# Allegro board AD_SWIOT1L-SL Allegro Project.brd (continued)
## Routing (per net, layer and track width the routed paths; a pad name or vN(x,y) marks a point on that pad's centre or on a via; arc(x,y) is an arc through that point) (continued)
AD74413R_GPO_A_ISO: length 40.2
  TOP w0.178: U2.19 31.37,39.61 32.81,41.06 32.81,43.77 34.74,45.7 42.28,45.7 v1(44.16,47.58) ; U14.16 v1(48.65,66.31)
  BOTTOM w0.178: v1(48.65,66.31) 48.65,52.07 v1(44.16,47.58)
AD74413R_GPO_B: length 33.9
  TOP w0.178: v1(43.46,91.31) 41.57,93.2 35.93,93.2 33.65,95.49 31.36,95.49 31.06,95.19 U1.46 ; U14.6 v1(48,76.01)
  BOTTOM w0.178: v1(43.46,91.31) 43.46,84.76 48,80.22 v1(48,76.01)
AD74413R_GPO_B_ISO: length 40
  TOP w0.178: U2.20 30.87,39.65 32.4,41.19 32.4,43.91 34.58,46.08 41.89,46.08 v1(43.45,47.65) ; U14.15 v1(48,65.97)
  BOTTOM w0.178: v1(43.45,47.65) 48,52.19 v1(48,65.97)
AD74413R_GPO_C: length 31.9
  TOP w0.178: U1.48 33.32,94.19 35.4,92.11 40.78,92.11 42.81,90.08 v1(42.92,90.08) ; U14.7 v1(47.35,76.39)
  BOTTOM w0.178: v1(42.92,90.08) 42.92,84.69 47.35,80.26 v1(47.35,76.39)
AD74413R_GPO_C_ISO: length 39.8
  TOP w0.178: U14.14 v1(47.35,66.31) ; v1(43.41,48.41) 41.47,46.47 34.42,46.47 32.02,44.06 32.02,41.4 30.37,39.74 U2.21
  BOTTOM w0.178: v1(47.35,66.31) 47.35,52.34 v1(43.41,48.41)
AD74413R_GPO_D: length 30.8
  TOP w0.178: v1(42.33,89.57) 40.43,91.47 35.17,91.47 32.96,93.69 U1.49 ; v1(46.7,76.01) U14.8
  BOTTOM w0.178: v1(46.7,76.01) 46.7,80.3 42.33,84.67 v1(42.33,89.57)
AD74413R_GPO_D_ISO: length 39.6
  TOP w0.178: U14.13 v1(46.7,65.29) ; U2.22 29.87,39.79 31.64,41.57 31.64,44.22 34.26,46.85 40.99,46.85 v1(42.61,48.47)
  BOTTOM w0.178: v1(42.61,48.47) 46.7,52.56 v1(46.7,65.29)
AD74413R_LDAC: length 31.4
  TOP w0.152: v1(54.47,78.42) 46.29,78.42 45.45,79.26 U1.100
  TOP w0.203: v1(58.73,60.44) U25.37
  BOTTOM w0.152: v1(54.47,78.42) 56.66,76.23 56.66,65.36 58.73,63.29 v1(58.73,60.44)
AD74413R_LDAC_ISO: length 63
  TOP w0.203: U2.58 29.37,28.72 30.5,27.59 30.5,23.43 31.94,21.98 43.12,21.98 v1(49.98,28.84) ; v1(64.63,51.41) 63.93,51.41 63.73,51.61 U25.22 ; R78.1 55.01,46.27 v1(55.01,45.54)
  BOTTOM w0.203: v1(64.63,51.41) 61.5,51.41 55.63,45.54 v1(55.01,45.54) 55.01,43.67 50.99,39.66 50.99,29.85 v1(49.98,28.84)
AD74413R_RESET: length 30.6
  TOP w0.152: U1.103 46.95,79.31 47.31,78.95 54.7,78.95 v1(55.26,78.39)
  TOP w0.203: v1(59.38,60.87) 59.38,60.31 59.23,60.16 U25.36
  BOTTOM w0.152: v1(59.38,60.87) 59.38,63.46 57.04,65.79 57.04,76.62 v1(55.26,78.39)
AD74413R_RESET_ISO: length 61.4
  TOP w0.203: R75.2 v1(54.88,47.41) ; v1(64.84,52.12) U25.23 ; v1(47.06,30.95) 47.06,29.37 41.54,23.86 32.91,23.86 32.2,24.57 32.2,28.23 31.37,29.06 U2.62
  BOTTOM w0.203: v1(47.06,30.95) 48.71,29.3 49.32,29.3 50.38,30.36 50.38,39.86 54.45,43.93 54.45,46.98 v1(54.88,47.41) 56.74,47.41 61.45,52.12 v1(64.84,52.12)
ADIN1110_RESET: length 15.9
  TOP w0.178: U1.121 50.38,88.19 50.37,88.18 50.09,88.18 v1(49.71,87.8) ; U8.5 v1(60.7,83.3)
  BOTTOM w0.178: v1(60.7,83.3) 57.77,83.3 56.2,84.87 53.51,84.87 50.57,87.8 v1(49.71,87.8)
ADT75_OS__ALLERT: length 24.2
  TOP w0.203: v1(13.65,102.26) U4.3 15.92,102.26 R94.2 ; v1(28.34,98.26) 28.77,98.69 U1.39
  BOTTOM w0.203: v1(13.65,102.26) 13.09,102.26 12.4,101.56 12.4,100.63 14.77,98.26 v1(28.34,98.26)
ALDO1V8: length 6.5
  TOP w0.279: U2.10 36.11,35.22 36.69,35.79 C22.1 C25.2
ALDO5V: length 4.6
  TOP w0.279: C21.1 36.83,35.21 36.34,34.72 U2.9
CABLE+: length 10.2
  TOP w0.762: 89.93,92.67 P3.1 ; P3.1 91.18,93.91 ; P3.1 89.93,95.16 ; P3.1 88.69,93.91
  TOP w0.787: R73.1 89.38,86.15 90.57,87.33 L1.4
CABLE-: length 10.2
  TOP w0.762: P3.2 92.5,93.91 ; P3.2 93.74,92.67 ; P3.2 93.74,95.16 ; P3.2 94.99,93.91
  TOP w0.787: L1.3 93.11,87.33 94.29,86.15 R74.1
CASCODE_A: length 6.4
  TOP w0.305: Q1.3 33.42,25.03 33.11,25.34 33.11,29.64 32.81,29.95 U2.64
CASCODE_B: length 4.1
  TOP w0.305: U2.17 32.97,38.99 34.22,40.23 Q2.3
CASCODE_C: length 6.4
  TOP w0.305: Q3.3 23.82,43.9 24.12,43.6 24.12,39.29 24.42,38.99 U2.32
CASCODE_D: length 4.1
  TOP w0.305: U2.49 24.36,29.95 23.01,28.6 Q4.3
CCOMP_A: length 16.6
  TOP w0.254: U2.63 31.87,29.45 v1(32.5,28.81)
  TOP w0.305: v1(40.58,28.08) 41.09,28.58 C1.1
  BOTTOM w0.254: v1(40.58,28.08) 40.58,26.55 37.99,23.96 35.22,23.96 32.5,26.68 v1(32.5,28.81)
CCOMP_B: length 13
  TOP w0.254: U2.18 31.87,39.45 32.45,40.04 v1(33.01,40.04)
  TOP w0.279: v1(41.07,40.65) C4.1
  BOTTOM w0.305: v1(41.07,40.65) 39.39,42.33 34.64,42.33 33.01,40.69 v1(33.01,40.04)
CCOMP_C: length 17
  TOP w0.279: U2.31 25.37,39.49 v1(24.73,40.12)
  TOP w0.305: C2.1 v1(16.14,41.11)
  BOTTOM w0.305: v1(24.73,40.12) 24.73,42.6 22.21,45.12 19.27,45.12 16.14,42 v1(16.14,41.11)
CCOMP_D: length 12.7
  TOP w0.279: v1(16.16,28.29) C3.1 ; v1(24.65,28.56) 25.37,29.27 U2.50
  BOTTOM w0.254: v1(16.16,28.29) 17.87,26.58 22.67,26.58 v1(24.65,28.56)
CH_1: length 13.3
  TOP w0.483: R9.2 R1.2 R17.1
  TOP w0.635: P6.1 41.95,8.11 ; P6.1 41.95,5.62 ; P6.1 40.71,6.87 ; P6.1 43.2,6.87
  TOP w0.762: v1(45.2,30.49) v1(44.49,30.49) C1.2 39.73,30.49 R17.1
  vias: v1(34.87,18.33) v1(34.87,17.56) v1(35.02,53.45) v1(35.02,52.69) v1(35.69,18.33) v1(35.69,17.56) v1(35.78,53.45) v1(35.78,52.69)
CH_2: length 10.9
  TOP w0.483: R18.1 R3.2 R11.2
  TOP w0.635: P6.3 35.58,6.87 ; P6.3 34.33,5.62 ; P6.3 34.33,8.11 ; P6.3 33.09,6.87
  TOP w0.762: R18.1 39.73,38.22 C4.2 v1(42.18,38.22) v1(42.89,38.22)
  vias: v1(27.25,18.33) v1(27.25,17.56) v1(28.07,18.33) v1(28.07,17.56) v1(34.95,59.15) v1(34.95,58.39) v1(35.71,59.15) v1(35.71,58.39)
CH_3: length 11.4
  TOP w0.483: R19.1 R5.2 R13.2
  TOP w0.635: P6.5 26.71,8.11 ; P6.5 26.71,5.62 ; P6.5 27.96,6.87 ; P6.5 25.47,6.87
  TOP w0.762: v1(13.86,38.44) v1(14.57,38.44) C2.2 17.5,38.44 R19.1
  vias: v1(19.63,18.33) v1(19.63,17.56) v1(20.45,18.33) v1(20.45,17.56) v1(21.5,59.15) v1(21.51,58.39) v1(22.17,59.15) v1(22.17,58.39)
CH_4: length 13.9
  TOP w0.483: R15.2 R7.2 R20.1
  TOP w0.635: P6.7 20.34,6.87 ; P6.7 17.85,6.87 ; P6.7 19.09,8.11 ; P6.7 19.09,5.62
  TOP w0.762: v1(11.34,30.72) v1(12.05,30.72) C3.2 17.5,30.72 R20.1
  vias: v1(12.01,18.33) v1(12.01,17.56) v1(12.83,18.33) v1(12.83,17.56) v1(21.46,53.46) v1(21.46,52.7) v1(22.22,53.46) v1(22.22,52.7)
DATA_AND_POWER_N: length 28.3
  TOP w0.305: R71.2 81.39,84.77 C46.2 v1(82.7,84.98)
  TOP w0.787: L1.2 93.11,83.27 94.29,84.45 R74.2
  BOTTOM w0.305: v1(93.11,79.99) 92.5,79.99 92.12,80.37 92.12,82.28 90.92,83.47 81.09,83.47 80.41,84.16 80.41,85.3 81.07,85.96 82.32,85.96 82.7,85.59 v1(82.7,84.98)
DATA_AND_POWER_P: length 29.2
  TOP w0.305: R72.2 81.39,87.68 C45.2 v1(82.7,87.47)
  TOP w0.787: L1.1 90.57,83.27 89.38,84.45 R73.2
  BOTTOM w0.305: v1(82.7,87.47) 82.7,86.86 82.33,86.5 80.81,86.5 79.87,85.56 79.87,83.93 80.86,82.94 90.69,82.94 91.57,82.06 91.57,80.39 91.18,79.99 v1(90.57,79.99)
DATA_N: length 7.2
  TOP w0.305: R71.1 79.89,84.77 C46.1 78.68,84.98 78.33,85.33 D19.1 R23.2 R24.2
DATA_P: length 7.2
  TOP w0.305: R22.2 R25.2 D5.1 78.33,87.12 78.68,87.47 C45.1 79.89,87.68 R72.1
DLDO1V8: length 3.5
  TOP w0.254: U2.57 28.87,28.36
  TOP w0.508: 28.87,28.36 C23.1 C130.2
DLDO_1P1: length 4
  TOP w0.254: U8.23 62.2,90.92 61.95,91.17 61.7,90.92 U8.24
  TOP w0.457: 61.95,91.17 61.95,92.09 C60.2 C58.1
FIELD_POWER_DETECTED: length 43.4
  TOP w0.152: v1(22.95,75.04) 22.95,76.13 23.74,76.92 26.74,76.92 31.94,82.13 39.87,82.13 40.45,81.54 U1.90
  TOP w0.203: U18.6 4.79,75.39 v1(4.79,75.4)
  BOTTOM w0.203: v1(4.79,75.4) 5.32,75.93 6.57,75.93 7.85,74.65 22.56,74.65 v1(22.95,75.04)
FIELD_POWER_DETECTED_ISO: length 83.5
  TOP w0.203: U18.3 v1(4.79,66.94) ; v1(51.68,54.06) 51.58,53.96 51.58,44.03 v1(55.9,39.71)
  BOTTOM w0.203: v1(55.9,39.71) 55.9,37.37 S2.2 ; v1(4.79,66.94) 5.19,66.54 9.15,66.54 10.4,67.8 48.61,67.8 49.62,66.79 49.62,56.12 v1(51.68,54.06)
FLED: length 46.7
  TOP w0.178: DS2.C 5.58,43.62 v1(5.58,43.62) 4.97,44.23 4.97,46.26 5.5,46.8 11.22,46.8 14.34,49.92 25.51,49.92 27.33,51.74 U3.4 ; v1(5.58,38.54) 5.58,38.54 DS4.C ; DS6.C 5.58,33.46 v1(5.58,33.46) ; DS8.C v1(5.58,28.38)
  BOTTOM w0.305: v1(5.58,28.38) v1(5.58,33.46) v1(5.58,38.54) v1(5.58,43.62)
G1: length 11
  TOP w0.203: U3.18 32.13,55.72 39.26,55.72 39.78,55.2 39.78,53.01 39.58,52.81 Q6.4
G2: length 7.5
  TOP w0.203: U3.19 32.11,56.15 38.4,56.15 38.96,56.71 Q5.4
G3: length 11.1
  TOP w0.203: Q7.4 17.53,59.06 17.33,58.85 17.33,56.69 17.87,56.15 25.06,56.15 U3.42
G4: length 7.6
  TOP w0.203: U3.43 25.04,55.72 18.69,55.72 18.16,55.18 Q8.4
GATE: length 7.5
  TOP w0.254: U19.12 93.09,55.74 93.76,55.74 v1(93.77,55.74)
  TOP w0.305: Q9.4 v1(97.96,55.31) 98.7,54.57 R40.2
  BOTTOM w0.305: v1(93.77,55.74) 97.52,55.74 v1(97.96,55.31)
HYP_CLK: length 45
  TOP w0.152: v1(18,94.57) 17.52,94.57 17.06,94.11 17.06,91.71 17.31,91.45 17.31,90.77 17.47,90.62 U10.B2 ; v1(23.66,94.22) 23.99,93.88 23.99,88.73 26.99,85.73 29.92,85.73 U1.65 ; U9.B2 6.04,90.62 5.89,90.77 5.89,91.45 5.64,91.71 5.64,94.11 6.1,94.57 v1(6.58,94.57)
  BOTTOM w0.152: v1(6.58,94.57) 6.58,95.05 7.88,96.35 10.63,96.35 12.87,94.12 17.06,94.12 17.52,94.57 v1(18,94.57) 18,95.05 18.61,95.67 20.3,95.67 20.73,95.23 21.29,95.23 21.72,95.67 23.48,95.67 23.99,95.16 23.99,94.55 v1(23.66,94.22)
HYP_CLKN: length 45
  TOP w0.152: U10.B1 16.91,90.77 16.91,91.28 16.65,91.54 16.65,94.28 17.23,94.86 v1(17.23,95.34) ; v1(24.74,94.22) 24.4,93.88 24.4,88.9 27.16,86.14 29.92,86.14 U1.64 ; v1(5.81,95.34) 5.81,94.86 5.23,94.28 5.23,91.54 5.48,91.28 5.48,90.77 U9.B1
  BOTTOM w0.152: v1(24.74,94.22) 24.4,94.56 24.4,95.33 23.65,96.07 18.45,96.07 17.71,95.34 v1(17.23,95.34) 17.23,94.86 16.9,94.52 13.04,94.52 10.8,96.76 7.71,96.76 6.29,95.34 v1(5.81,95.34)
HYP_CS0N: length 29.3
  TOP w0.152: v1(19.4,93.2) 18.76,92.57 U10.A3 ; U1.52 v1(31.18,92.19)
  BOTTOM w0.152: v1(19.4,93.2) 19.88,92.72 20.15,92.72 20.77,93.34 21.01,93.34 21.21,93.14 21.21,92.92 20.8,92.52 20.8,92.3 21.02,92.08 21.24,92.08 21.63,92.48 21.87,92.48 22.07,92.27 22.07,92.06 21.67,91.65 21.67,91.44 21.88,91.22 22.1,91.22 22.57,91.69 22.81,91.69 23.01,91.49 23.01,91.27 22.53,90.79 22.53,90.57 22.75,90.36 22.96,90.36 23.46,90.85 23.7,90.85 23.9,90.65 23.9,90.44 23.39,89.93 23.39,89.71 23.69,89.42 24.29,89.42 24.44,89.57 24.44,90.13 24.6,90.28 24.9,90.28 25.05,90.13 25.05,89.57 25.21,89.42 27.8,89.42 28.17,89.79 28.17,90 27.8,90.37 27.8,90.61 28.01,90.81 28.22,90.81 28.6,90.43 28.82,90.43 29.03,90.65 29.03,90.86 28.6,91.3 28.6,91.51 28.82,91.73 29.03,91.73 29.47,91.29 29.68,91.29 29.9,91.51 29.9,91.73 29.51,92.11 29.51,92.32 29.73,92.54 29.95,92.54 30.3,92.19 v1(31.18,92.19)
HYP_CS1N: length 29.3
  TOP w0.152: v1(8.1,95.11) R82.2 8.1,93.06 7.34,92.29 U9.A3 ; U1.44 v1(28.74,96.19)
  BOTTOM w0.152: v1(8.1,95.11) 10,93.2 18.48,93.2 19.09,93.81 21.2,93.81 22.04,92.97 27.09,92.97 28.21,94.09 28.21,95.65 v1(28.74,96.19)
HYP_D0: length 42.2
  TOP w0.152: v2(32.71,87.94) 32.71,89.98 30.99,91.69 U1.53 ; U10.D3 v2(18.29,89.09) ; U9.D3 v2(6.87,89.09)
  BOTTOM w0.152: v2(32.71,87.94) 32.71,87 29.38,83.68 25.92,83.68 24.79,84.81 23.56,84.81 23.41,84.96 23.41,85.28 23.25,85.43 22.95,85.43 22.8,85.28 22.8,84.96 22.65,84.81 22.1,84.81 18.79,88.12 18.79,88.59 v2(18.29,89.09) 17.79,89.6 16.75,89.6 16.22,90.13 15.53,90.13 15,89.59 13.58,89.59 10.15,86.17 9.26,86.17 7.71,87.72 7.71,88.6 7.23,89.09 v2(6.87,89.09)
HYP_D1: length 42.1
  TOP w0.152: U9.D2 v2(5.87,89.09) ; U1.58 31.11,89.19 31.82,88.48 31.82,87.74 32.76,86.8 33.18,86.8 v2(33.2,86.82) ; U10.D2 v2(17.29,89.09)
  BOTTOM w0.152: v2(33.2,86.82) 32.68,86.3 32.68,86.29 29.58,83.19 23.08,83.19 20.41,85.87 20.19,85.87 19.97,85.65 19.76,85.65 19.54,85.87 19.54,86.08 19.76,86.3 19.76,86.51 18.53,87.74 18.07,87.74 17.29,88.51 v2(17.29,89.09) 16.95,89.09 16.56,88.7 13.22,88.7 11.65,87.12 11.65,86.34 11.01,85.71 9.08,85.71 7.13,87.66 6.62,87.66 6.36,87.92 6.36,88.6 v2(5.87,89.09)
HYP_D2: length 42.2
  TOP w0.152: U1.62 31.05,87.19 32.68,85.56 34.13,85.56 34.43,85.86 v2(34.43,87.89) ; U10.C4 v2(20.23,90.09) ; U9.C4 v2(8.8,90.09)
  BOTTOM w0.152: v2(8.8,90.09) 10.46,90.09 11.35,90.97 11.35,91.19 10.98,91.56 10.98,91.77 11.2,91.99 11.42,91.99 11.78,91.62 12,91.62 12.72,92.34 18.86,92.34 19.73,91.47 19.73,90.59 v2(20.23,90.09) 20.96,90.09 22.47,88.58 24.78,88.58 25.8,87.56 28.97,87.56 29.28,87.88 29.28,89.44 30.37,90.53 31.79,90.53 v2(34.43,87.89)
HYP_D3: length 42.1
  TOP w0.152: v2(32.58,83.93) 31.32,85.19 U1.66 ; U10.D4 v2(20.23,88.15) ; U9.D4 v2(8.8,88.15)
  BOTTOM w0.152: v2(8.8,88.15) 9.23,88.58 10.43,88.58 13.35,91.5 18.51,91.5 18.8,91.2 18.8,90.19 19.73,89.26 19.73,88.65 v2(20.23,88.15) 20.74,87.64 24.45,87.64 25.52,86.57 28.95,86.57 29.99,85.53 30.57,85.53 32.07,87.03 32.07,88.15 32.43,88.5 33,88.5 34.51,87 34.51,84.51 33.92,83.93 v2(32.58,83.93)
HYP_D4: length 42.3
  TOP w0.152: U10.D5 v2(21.23,88.15) ; U1.56 31.22,90.19 v2(31.74,89.67) ; U9.D5 v2(9.8,89.09)
  BOTTOM w0.152: v2(9.8,89.09) 10.2,89.09 13.02,91.91 18.71,91.91 19.27,91.35 19.27,90.33 20.05,89.54 20.69,89.54 21.23,89.01 v2(21.23,88.15) 24.65,88.15 25.75,87.05 29.11,87.05 30.2,85.96 30.42,85.96 30.63,86.18 30.63,86.39 29.65,87.37 29.65,87.59 29.87,87.8 30.09,87.8 31.06,86.82 31.28,86.82 31.47,87.01 31.47,87.28 29.67,89.08 29.67,89.3 29.87,89.5 30.11,89.5 31.39,88.22 31.61,88.22 31.82,88.44 31.82,88.65 30.77,89.71 30.77,89.92 31.02,90.17 31.24,90.17 v2(31.74,89.67)
HYP_D5: length 42.2
  TOP w0.152: U9.E3 v2(6.87,87.15) ; U10.E3 v2(18.29,87.15) ; U1.59 30.97,88.69 31.38,88.27 31.38,87.54 32.83,86.09 v2(33.19,86.09)
  BOTTOM w0.152: v2(6.87,87.15) 8.8,85.23 11.27,85.23 12.16,86.11 12.16,86.88 12.77,87.49 13.73,87.49 13.88,87.65 13.88,87.94 14.03,88.1 14.34,88.1 14.49,87.94 14.49,87.65 14.64,87.49 15.01,87.49 15.69,88.17 17.01,88.17 18.03,87.15 v2(18.29,87.15) 18.83,86.62 18.83,85.49 19.57,84.74 19.79,84.74 20.09,85.05 20.31,85.05 20.53,84.83 20.53,84.62 20.22,84.31 20.22,84.1 20.44,83.88 20.65,83.88 20.96,84.19 21.2,84.19 21.4,83.98 21.4,83.77 21.08,83.45 21.08,83.23 21.58,82.74 29.83,82.74 v2(33.19,86.09)
HYP_D6: length 42.1
  TOP w0.152: U1.63 30.86,86.69 v2(32.7,84.84) ; U10.E2 v2(17.29,87.15) ; U9.E2 v2(5.87,87.15)
  BOTTOM w0.152: v2(5.87,87.15) 6.39,86.63 6.39,86.01 7.74,84.67 14.19,84.67 14.9,85.38 14.9,86.57 16.02,87.69 16.76,87.69 v2(17.29,87.15) 17.8,86.64 17.8,84.71 18.27,84.24 18.49,84.24 18.84,84.6 19.06,84.6 19.27,84.38 19.27,84.17 18.91,83.8 18.91,83.56 19.11,83.35 19.32,83.35 19.71,83.73 19.92,83.73 20.14,83.52 20.14,83.3 19.78,82.95 19.78,82.73 20.32,82.19 30.05,82.19 v2(32.7,84.84)
HYP_D7: length 42.1
  TOP w0.152: U10.E1 v2(16.29,87.15) ; U9.E1 v2(4.87,87.15) ; U1.67 31.03,84.69 31.94,83.78 v2(31.94,83.27)
  BOTTOM w0.152: v2(4.87,87.15) 5.35,86.67 5.35,85.89 7.13,84.11 14.49,84.11 15.48,85.1 15.48,86.35 16.29,87.16 v2(16.29,87.15) 16.77,86.67 16.77,84.88 17.21,84.44 17.21,84.22 16.9,83.92 16.9,83.7 17.12,83.49 17.34,83.49 17.64,83.79 17.86,83.79 18.07,83.58 18.07,83.36 17.79,83.08 17.79,82.87 18.01,82.65 18.22,82.65 18.5,82.93 18.72,82.93 18.94,82.71 18.94,82.5 18.68,82.24 18.68,82.03 18.9,81.81 19.11,81.81 19.37,82.07 19.58,82.07 19.98,81.67 30.34,81.67 v2(31.94,83.27)
HYP_RESET: length 33
  TOP w0.152: U1.50 31.86,93.19 32.32,92.72 v2(32.32,91.27) ; U9.A4 v2(8.8,92.09) ; U10.A4 v2(20.26,92.12)
  BOTTOM w0.152: v2(32.32,91.27) 32.04,90.99 30.06,90.99 28.64,89.57 28.64,88.81 27.85,88.02 25.97,88.02 25,88.99 23.4,88.99 v2(20.26,92.12) 19.71,92.12 19.04,92.8 9.51,92.8 v2(8.8,92.09)
HYP_RWDS: length 42.2
  TOP w0.152: U10.C3 v2(18.29,90.09) ; U9.C3 v2(6.87,90.09) ; U1.68 28.39,84.19 v2(28.18,84.39)
  BOTTOM w0.152: v2(6.87,90.09) 8.17,88.79 8.17,87.94 9.48,86.63 10.03,86.63 14.01,90.61 17.08,90.61 17.77,90.61 v2(18.29,90.09) 19.27,89.11 19.27,88.35 21.6,86.01 23.46,86.01 23.66,86.21 23.66,86.72 23.89,86.95 24.48,86.95 24.73,86.7 24.73,85.35 24.88,85.2 25.21,85.2 25.36,85.35 25.36,85.73 25.51,85.89 25.82,85.89 25.97,85.73 25.97,84.26 26.12,84.11 26.43,84.11 26.58,84.26 26.58,85.73 26.73,85.89 27.04,85.89 27.19,85.73 27.19,84.67 27.34,84.51 27.65,84.51 27.8,84.67 27.8,85.73 27.95,85.89 29.05,85.89 29.35,85.58 29.35,84.62 29.12,84.39 v2(28.18,84.39)
I2C1_SCL: length 34.4
  TOP w0.203: v1(39.63,98.59) 39.95,98.92 U1.20 ; v1(13.34,101.61) U4.2 R95.2
  BOTTOM w0.203: v1(13.34,101.61) 15.58,99.36 35.03,99.36 36.44,97.95 38.99,97.95 v1(39.63,98.59)
I2C1_SDA: length 36.1
  TOP w0.203: v1(13.04,100.96) U4.1 15.92,100.96 R96.2 ; U1.19 v1(40.45,98.59)
  BOTTOM w0.203: v1(40.45,98.59) 39.26,97.39 36.18,97.39 34.66,98.92 15.07,98.92 v1(13.04,100.96)
INT: length 13.9
  TOP w0.178: v1(50.22,91.19) U1.127 ; U8.25 61.2,91.25 v1(61.2,91.25)
  BOTTOM w0.178: v1(50.22,91.19) 53.4,91.19 54.24,92.03 60.42,92.03 v1(61.2,91.25)
L1: length 37.2
  TOP w0.178: U3.8 29.33,51.13 26.3,48.09 15.03,48.09 9.59,42.65 9.59,33.46 8.52,32.39 8.52,31.2 8.27,30.95 R33.2
L2: length 32.1
  TOP w0.178: R32.2 8.63,36.03 9.08,36.48 9.08,42.78 14.85,48.55 26.09,48.55 28.83,51.29 U3.7
L3: length 26.6
  TOP w0.178: U3.6 28.33,51.46 25.88,49.01 14.67,49.01 8.6,42.93 8.6,41.38 8.32,41.11 R31.2
L4: length 23
  TOP w0.178: R30.2 11.26,46.19 14.54,49.46 25.7,49.46 27.83,51.6 U3.5
LED1: length 28.7
  TOP w0.254: v1(54.51,99.26) 54.08,99.69 U1.144
  TOP w0.305: Q20.1 v1(76.94,102.85)
  BOTTOM w0.254: v1(54.51,99.26) 54.92,98.85 59.61,98.85 61.51,100.75 69.66,100.75 71.76,102.85 v1(76.94,102.85)
LED2: length 28.8
  TOP w0.254: v1(53.75,98.78) 53.38,99.15 51.48,99.15 U1.143
  TOP w0.305: Q21.1 v1(76.94,97.77)
  BOTTOM w0.254: v1(76.94,97.77) 72.18,97.77 69.69,100.26 61.72,100.26 61.67,100.21 61.66,100.21 59.81,98.36 54.16,98.36 v1(53.75,98.78)
LGATE1: length 5.4
  TOP w0.254: U19.9 91.59,54.62 91.23,54.26 91.23,51.82 90.72,51.32 Q12.2
LGATE2: length 2.3
  TOP w0.254: Q12.4 90.11,53.86 91.09,54.83 U19.8
LINK_ST: length 24.3
  TOP w0.178: U8.4 60.2,83.62 60.06,83.47 v1(60.06,82.38) ; v1(48.86,92.69) U1.130
  BOTTOM w0.178: v1(60.06,82.38) 59.67,81.99 57.53,81.99 55.67,83.85 53.1,83.85 50.79,86.17 49.72,86.17 48.3,87.59 48.3,92.13 v1(48.86,92.69)
MAX14906_D1: length 22.9
  TOP w0.178: R129.2 37.1,75.12 v1(37.1,75.12) U12.6 ; U1.97 43.95,81.6 42.76,82.79 v1(42.23,82.79)
  BOTTOM w0.178: v1(42.23,82.79) 42.79,82.23 42.79,81.52 43.71,80.6 43.71,76.28 44.47,75.52 44.47,74.66 43.88,74.08 38.88,74.08 38.39,74.56 37.66,74.56 v1(37.1,75.12)
MAX14906_D1_ISO: length 19.1
  TOP w0.178: v1(33.77,62.19) 34.53,62.19 37.1,64.76 R132.2 R50.1 U12.11 ; v1(32.32,52.56) 32.08,52.8 U3.13
  BOTTOM w0.178: v1(32.32,52.56) 32.32,59.47 33.77,60.92 v1(33.77,62.19)
MAX14906_D2: length 18.2
  TOP w0.178: R127.2 v1(38.37,75.12) U12.5 ; U1.96 43.45,81.24 43.17,81.52 v1(42.23,81.52)
  BOTTOM w0.178: v1(38.37,75.12) 39.04,74.46 43.7,74.46 44.08,74.84 44.08,75.35 43.33,76.1 43.33,80.42 v1(42.23,81.52)
MAX14906_D2_ISO: length 13.2
  TOP w0.178: U12.12 R52.1 R134.2 38.37,64.35 34.89,60.87 33.74,60.87 32.08,59.21 U3.24
MAX14906_D3: length 23.9
  TOP w0.178: R130.2 v1(26.43,75.12) U13.6 ; v1(42.28,77.22) 42.95,77.9 U1.95
  BOTTOM w0.178: v1(26.43,75.12) 27,74.56 27.7,74.56 28.21,74.05 33.29,74.05 33.85,74.61 33.85,76.01 34.33,76.49 41.54,76.49 v1(42.28,77.22)
MAX14906_D3_ISO: length 11.7
  TOP w0.178: U3.37 24.79,58.68 24.58,58.89 24.58,59.6 23.79,60.38 23.79,62.03 26.43,64.67 R133.2 R51.1 U13.11
MAX14906_D4: length 21.6
  TOP w0.178: U13.5 v1(27.7,75.12) R128.2 ; v1(41.51,77.29) 42.45,78.24 U1.94
  BOTTOM w0.178: v1(41.51,77.29) 41.11,76.89 34.15,76.89 33.47,76.21 33.47,74.79 33.13,74.46 28.37,74.46 v1(27.7,75.12)
MAX14906_D4_ISO: length 18.5
  TOP w0.178: v1(25.21,52.54) 25.21,53.05 U3.48 ; U13.12 R53.1 R135.2 27.7,65.21 24.27,61.78 24.27,60.66 25.16,59.78 v1(25.16,59.29)
  BOTTOM w0.178: v1(25.21,52.54) 25.21,59.24 25.16,59.29 v1(25.16,59.29)
MAX14906_EN: length 16.1
  TOP w0.152: U1.72 28.92,82.19 28.49,81.75 28.49,79.33 26.43,77.28 20.28,77.28 19.93,76.92 19.93,76.28 19.35,75.7 U7.15
MAX14906_EN_ISO: length 17.6
  TOP w0.178: v1(20.31,66.13) 19.7,66.13 19.35,66.48 U7.6 ; v1(30.11,60.94) 30.11,60.51 30.33,60.29 U3.27
  BOTTOM w0.178: v1(30.11,60.94) 30.67,61.5 30.67,62.57 28.59,64.65 21.78,64.65 v1(20.31,66.13)
MAX14906_FAULT: length 18.7
  TOP w0.152: U7.17 18.05,75.83 17.77,76.11 17.77,77.49 17.91,77.63 26.08,77.63 28.06,79.61 28.06,81.95 28.79,82.69 U1.71
MAX14906_FAULT_ISO: length 18
  TOP w0.178: R69.2 v1(18.55,65.73) 18.05,66.23 U7.4 ; U3.29 29.33,61.18 v1(29.55,61.4)
  BOTTOM w0.178: v1(18.55,65.73) 19.31,65.73 21.28,63.76 27.62,63.76 29.55,61.83 v1(29.55,61.4)
MAX14906_READY: length 19.2
  TOP w0.152: U1.70 28.66,83.19 27.6,82.13 27.6,79.84 25.75,77.99 17.72,77.99 17.4,77.67 U7.18
MAX14906_READY_ISO: length 21.2
  TOP w0.178: U3.26 30.83,61.13 v1(30.13,61.83) ; R70.1 v1(16.84,65.73) 17.4,66.29 U7.3
  BOTTOM w0.178: v1(16.84,65.73) 17.42,66.3 19.34,66.3 21.38,64.27 28.03,64.27 30.13,62.18 v1(30.13,61.83)
MAX14906_SYNCH: length 27.4
  TOP w0.152: R37.1 v1(18.32,76.33) 18.7,75.95 18.7,75.89 18.7,75.89 U7.16
  TOP w0.178: U1.91 40.95,79.15 v1(40.49,78.69)
  BOTTOM w0.178: v1(18.32,76.33) 19.32,77.33 32.9,77.33 33.62,78.04 39.85,78.04 v1(40.49,78.69)
MAX14906_SYNCH_ISO: length 12.9
  TOP w0.178: v1(22.75,61.65) 22.75,63.61 20.79,65.57 19.61,65.57 18.7,66.48 U7.5 ; U3.36 25.83,59.94 24.82,60.96 v1(24.82,61.25)
  BOTTOM w0.178: v1(22.75,61.65) 24.42,61.65 v1(24.82,61.25)
MAXQ1065_PDWN: length 21.5
  TOP w0.178: v1(48.45,99.55) U1.3 ; U5.7 64.45,96.69 v1(64.71,96.43)
  BOTTOM w0.178: v1(64.71,96.43) 63.63,95.36 63.62,95.36 63.57,95.31 58.43,95.31 56.81,96.94 52.15,96.94 50.4,98.69 49.32,98.69 v1(48.45,99.55)
MAXQ1065_RDY: length 20.7
  TOP w0.178: v1(49.72,100.44) 49.45,100.71 U1.1 ; U5.11 64.45,98.69 v1(64.71,98.94)
  BOTTOM w0.178: v1(49.72,100.44) 52.47,97.7 57.12,97.7 57.15,97.67 57.17,97.67 58.77,96.07 62.55,96.07 64.71,98.23 v1(64.71,98.94)
MAXQ1065_WDI: length 20.8
  TOP w0.178: U1.2 48.95,100.14 v1(49.22,99.88) ; v1(64.71,97.43) 64.45,97.69 U5.9
  BOTTOM w0.178: v1(49.22,99.88) 49.91,99.19 50.44,99.19 52.31,97.32 56.96,97.32 58.59,95.69 62.96,95.69 v1(64.71,97.43)
PMOD_IRQ: length 43.9
  TOP w0.178: U1.93 41.95,78.52 v1(41.56,78.13)
  TOP w0.203: U18.7 3.52,75.07 v1(3.85,75.4)
  BOTTOM w0.178: v1(3.85,75.4) 4.87,76.41 6.77,76.41 8.09,75.09 21.66,75.09 23.05,76.49 33.16,76.49 33.95,77.28 40.71,77.28 v1(41.56,78.13)
PMOD_IRQ_ISO: length 8.5
  TOP w0.203: U18.2 3.52,67.29 v1(3.88,66.94)
  BOTTOM w0.203: v1(3.88,66.94) 6.47,64.35 7.22,64.35 8.02,63.54 P2.1
POWER_N: length 0.8
  TOP w0.254: v1(92.59,59.24) U19.2
  vias: v1(84.5,55.1) v1(84.47,53.86) v1(84.47,52.59) v1(85.21,55.1) v1(85.18,53.86) v1(85.18,52.59) v1(87.78,72.2) v1(87.78,71.39) v1(88.54,72.2) v1(88.54,71.39)
POWER_P: length 1
  TOP w0.254: U19.1 93.09,58.69 v1(93.59,59.19)
  vias: v1(87.52,55.1) v1(87.52,50.96) v1(87.52,50.26) v1(88.23,55.1) v1(88.23,50.96) v1(88.23,50.26) v1(95.13,72.2) v1(95.13,71.39) v1(95.89,72.2) v1(95.89,71.39)
PWRGD: length 8.4
  TOP w0.305: Q13.1 57.42,65.86 58.36,64.92 58.36,62.85 59.95,61.26 R57.2 60.19,60.36 59.73,59.9 U25.35
REFOUT: length 3.3
  TOP w0.254: U2.29 U2.30 25.87,40.07 25.19,40.74 C106.2
RSTN: length 45.2
  TOP w0.178: R125.2 U1.114 49.51,84.69 v1(49.27,84.44) ; S1.1 v1(70.15,94.53) C180.2 ; R106.2 P1.10 v1(67.23,96.33)
  BOTTOM w0.178: v1(67.23,96.33) 68.35,96.33 v1(70.15,94.53) 70.6,94.08 70.6,87.92 63.82,81.14 52.57,81.14 v1(49.27,84.44)
RXN: length 10.9
  TOP w0.203: U8.13 69.58,86.1 69.83,85.85 R21.1 73.31,85.85 73.83,85.33 R23.1
RXP: length 10.8
  TOP w0.203: U8.14 R26.1 73.31,86.6 73.83,87.12 R25.1
SCCP: length 8
  TOP w0.254: Q11.1 85.49,57.67 86.15,57.01 87.82,57.01 88.5,57.68 Q10.1 89.05,57.91 89.58,57.39 89.58,55.97 90.05,55.5 U19.7
SENSEH_A: length 4.8
  TOP w0.279: U2.1 33.42,30.72 35.93,28.2 R2.1
SENSEH_B: length 4.7
  TOP w0.279: R4.1 35.81,40.48 33.55,38.22 U2.16
SENSEH_C: length 4.8
  TOP w0.279: U2.33 23.81,38.22 21.29,40.73 R6.1
SENSEH_D: length 4.7
  TOP w0.279: R8.1 21.55,28.46 23.82,30.72 U2.48
SENSEHF_A: length 5.1
  TOP w0.279: U2.2 33.7,31.22 35.09,29.83 C6.1 R10.1
SENSEHF_B: length 5
  TOP w0.279: U2.15 33.84,37.72 35,38.88 C8.1 R12.1
SENSEHF_C: length 5.1
  TOP w0.279: R14.1 C10.1 22.18,39.11 23.57,37.72 U2.34
SENSEHF_D: length 5
  TOP w0.279: R16.1 C12.1 22.27,30.06 23.43,31.22 U2.47
SENSEL_A: length 4.2
  TOP w0.279: U2.3 33.99,31.72 35.07,30.64 R1.1
SENSEL_B: length 4.1
  TOP w0.279: U2.14 34.15,37.22 34.99,38.06 36.87,38.06 R3.1
SENSEL_C: length 4.2
  TOP w0.279: R5.1 22.21,38.29 23.28,37.22 U2.35
SENSEL_D: length 4.1
  TOP w0.279: R7.1 22.24,30.87 23.09,31.72 U2.46
SENSELF_A: length 5.2
  TOP w0.279: U2.4 34.28,32.22 34.99,31.5 35.73,31.5 36.46,32.24 C5.1 R9.1
SENSELF_B: length 5.1
  TOP w0.279: U2.13 34.46,36.72 34.97,37.22 35.7,37.22 36.46,36.47 C7.1 R11.1
SENSELF_C: length 5.1
  TOP w0.279: U2.36 23.02,36.72 22.32,37.42 21.5,37.42 20.77,36.69 C9.1 R13.1
SENSELF_D: length 5.2
  TOP w0.279: U2.45 22.78,32.22 22.16,31.61 21.58,31.61 20.72,32.47 C11.1 R15.1
SLED: length 69.4
  TOP w0.178: DS5.C 6.29,34.98 6.28,34.98 v1(4.46,34.98) ; U3.9 29.83,50.93 26.56,47.66 15.23,47.66 10.12,42.55 10.12,33.23 9.04,32.15 9.04,27.73 8.55,27.24 5.04,27.24 4.46,27.82 v1(4.46,29.9) 6.39,29.9 DS7.C ; DS1.C v1(5.58,45.14) ; v1(4.46,40.06) 6.28,40.06 6.29,40.06 DS3.C
  BOTTOM w0.305: v1(5.58,45.14) 4.46,44.03 v1(4.46,40.06) v1(4.46,34.98) v1(4.46,29.9)
SLEW: length 8.5
  TOP w0.305: U25.32 v1(63.73,59.93)
  TOP w0.508: JP1.2 v1(64.38,66.1)
  BOTTOM w0.508: v1(64.38,66.1) 63.73,65.45 v1(63.73,59.93)
SPI0_MISO: length 10
  TOP w0.152: U1.138 52.51,96.69 53,97.18 59.23,97.18 59.74,97.69 U5.4
SPI0_MOSI: length 10
  TOP w0.152: U5.3 59.4,98.19 58.9,97.69 53.01,97.69 52.51,98.19 U1.141
SPI0_SCK: length 10
  TOP w0.152: U1.142 52.72,98.69 53.19,98.22 58.65,98.22 59.11,98.69 U5.2
SPI0_SS0: length 19.6
  TOP w0.178: U1.10 44.95,100.2 v1(46.31,98.84) ; v1(54.09,96.22) 54.53,96.66 59.41,96.66 59.93,97.19 U5.5
  BOTTOM w0.178: v1(46.31,98.84) 48.93,96.22 v1(54.09,96.22)
SPI1_MISO: length 48.4
  TOP w0.178: U6.17 v1(10.09,76.39) ; U1.117 39.48,86.19 v1(38.62,85.33)
  BOTTOM w0.178: v1(10.09,76.39) 12.92,79.22 31.19,79.22 32.81,80.83 35.47,80.83 37.25,82.61 37.25,84.82 37.76,85.33 v1(38.62,85.33)
SPI1_MISO_ISO: length 37.5
  TOP w0.178: P2.6 4.21,58.61 4.21,60.61 4.74,61.15 8.96,61.15 9.64,61.83 10.4,62.59 v1(10.4,65.77) 10.4,66.18 10.09,66.49 U6.4 ; v1(27.31,61.29) 27.83,60.77 U3.32
  BOTTOM w0.178: v1(10.4,65.77) 12,65.77 14.39,63.38 26.33,63.38 27.31,62.4 v1(27.31,61.29)
SPI1_MOSI: length 48.3
  TOP w0.178: U6.15 v1(11.39,76.39) ; v1(37.94,84.46) 37.94,85.63 38.99,86.69 U1.118
  BOTTOM w0.178: v1(11.39,76.39) 11.39,76.93 13.15,78.7 31.31,78.7 32.91,80.3 35.83,80.3 37.94,82.41 v1(37.94,84.46)
SPI1_MOSI_ISO: length 32.6
  TOP w0.178: U6.6 11.39,66.13 10.96,65.71 v1(10.96,64.86) 10.96,60.89 8.68,58.61 6.75,58.61 P2.4 ; U3.35 26.33,60.13 25.42,61.04 v1(25.42,61.63)
  BOTTOM w0.178: v1(10.96,64.86) 12.05,63.76 12.05,63.13 12.98,62.2 22.97,62.2 22.99,62.19 24.87,62.19 v1(25.42,61.63)
SPI1_SCK: length 46
  TOP w0.178: U6.14 v1(12.04,76.08) ; U1.115 40.42,85.19 v1(39.74,84.51)
  BOTTOM w0.178: v1(12.04,76.08) 12.04,76.63 13.64,78.23 31.52,78.23 33.06,79.76 36.13,79.76 38.52,82.15 38.52,83.93 39.1,84.51 v1(39.74,84.51)
SPI1_SCK_ISO: length 36.2
  TOP w0.178: U6.7 12.04,66.04 11.72,65.73 v1(11.72,65.19) 11.72,58.86 8.93,56.07 6.76,56.07 P2.8 ; U3.33 27.33,60.5 26.63,61.2 v1(26.63,61.63)
  BOTTOM w0.178: v1(26.63,61.63) 26.63,62.44 26.1,62.98 13.93,62.98 v1(11.72,65.19)
SPI1_SS2: length 24.9
  TOP w0.178: U7.13 v1(20.65,76.36) ; v1(40.57,77.95) 41.45,78.84 U1.92
  BOTTOM w0.178: v1(40.57,77.95) 40.28,77.66 33.78,77.66 33.04,76.92 21.21,76.92 v1(20.65,76.36)
SPI1_SS2_ISO: length 22.2
  TOP w0.178: P2.2 5.48,65.42 7.23,67.17 7.23,68.84 7.81,69.43 20.05,69.43 20.65,68.83 U7.8
SPI1_SS3: length 46
  TOP w0.178: U1.116 39.97,85.69 39.11,84.82 v1(39.11,83.6) ; U6.13 v1(12.69,76.39)
  BOTTOM w0.178: v1(12.69,76.39) 14.07,77.77 31.73,77.77 33.16,79.21 36.39,79.21 39.11,81.92 v1(39.11,83.6)
SPI1_SS3_ISO: length 21.1
  TOP w0.178: U6.8 v1(12.69,63.41) ; U3.34 26.83,60.34 26.02,61.15 v1(26.02,62.04)
  BOTTOM w0.178: v1(26.02,62.04) 25.46,62.59 13.5,62.59 v1(12.69,63.41)
SPI2_MISO__SPI_CFG1: length 17
  TOP w0.178: v1(58.07,82.75) 59.2,83.89 U8.2 ; v1(48.86,88.35) 49.25,88.74 49.95,88.74 50.4,89.19 U1.123
  BOTTOM w0.178: v1(48.86,88.35) 48.86,87.77 49.98,86.65 50.99,86.65 53.28,84.36 55.91,84.36 57.52,82.75 v1(58.07,82.75)
SPI2_MOSI: length 13.9
  TOP w0.178: U8.1 58.7,84.02 58.53,83.84 v1(58.11,83.84) ; v1(49.82,89.69) U1.124
  BOTTOM w0.178: v1(58.11,83.84) 58.11,84.67 56.33,86.45 53.61,86.45 50.37,89.69 v1(49.82,89.69)
SPI2_SCK: length 8.4
  TOP w0.152: U8.38 54.82,86.1 53.79,87.13 53.79,88.35 53.45,88.69 U1.122
SPI2_SS0: length 13.2
  TOP w0.178: U1.125 50.38,90.19 50.1,90.46 v1(49.52,90.46) ; U8.29 v1(59.2,91.37)
  BOTTOM w0.178: v1(49.52,90.46) 54.55,90.46 55.46,91.37 v1(59.2,91.37)
SPI3_MISO: length 57.4
  TOP w0.178: U1.35 32.45,99.8 36.95,95.31 43.42,95.31 44.49,94.24 v1(45.15,94.24) ; U25.1 55.66,58.37 55.34,58.69 v1(55.34,59.34)
  BOTTOM w0.178: v1(55.34,59.34) 55.34,59.89 55.03,60.19 55.03,74.87 45.15,84.75 v1(45.15,94.24)
SPI3_MISO_ISO: length 65.5
  TOP w0.203: v1(48.73,31.5) 50.76,29.47 50.76,28 43.83,21.07 29.38,21.07 25.31,25.13 25.31,28.48 25.87,29.03 U2.51 ; v1(53.34,52) R80.1 ; U25.7 55.21,52.87 v1(54.94,52.6)
  BOTTOM w0.203: v1(54.94,52.6) 53.94,52.6 v1(53.34,52) 51.55,50.21 51.55,43.37 48.73,40.55 v1(48.73,31.5)
SPI3_MOSI: length 57.3
  TOP w0.178: U1.36 31.95,99.46 36.74,94.67 42.97,94.67 44.08,93.56 45.13,93.56 v1(45.71,92.97) ; v1(55.89,59.97) 56.31,59.97 56.73,59.55 U25.41
  BOTTOM w0.178: v1(55.89,59.97) 55.44,60.43 55.44,75 45.71,84.73 v1(45.71,92.97)
SPI3_MOSI_ISO: length 54.9
  TOP w0.203: U25.8 56.73,51.59 v1(56.19,51.05) ; v1(53.34,50.1) R76.1 ; U2.60 30.37,28.89 31.33,27.92 31.33,23.99 32.43,22.89 42.36,22.89 48.48,29.02 v1(48.48,30.44)
  BOTTOM w0.203: v1(48.48,30.44) 49.29,31.25 49.29,40.34 52.01,43.06 52.01,48.77 v1(53.34,50.1) 54.29,51.05 v1(56.19,51.05)
SPI3_SCK: length 56.5
  TOP w0.178: v1(56.33,60.54) 57.23,59.63 U25.40 ; v1(46.27,93.66) 46.65,94.04 46.65,95.77 44.97,97.44 37.48,97.44 34.95,99.97 U1.30
  BOTTOM w0.178: v1(56.33,60.54) 55.84,61.02 55.84,75.14 46.27,84.71 v1(46.27,93.66)
SPI3_SCK_ISO: length 56.1
  TOP w0.203: v1(49.04,29.96) 49.04,28.71 42.76,22.44 32.2,22.44 30.9,23.73 30.9,27.77 29.87,28.81 U2.59 ; R77.2 53.08,48.97 v1(53.08,48.2) ; v1(57.01,51.04) 57.23,51.26 U25.9
  BOTTOM w0.203: v1(49.04,29.96) 49.8,30.72 49.8,40.09 52.42,42.71 52.42,47.54 v1(53.08,48.2) 54.8,49.92 55.9,49.92 v1(57.01,51.04)
SPI3_SS3: length 57.1
  TOP w0.178: v1(54.83,58.4) 55.36,57.87 U25.2 ; U1.32 33.95,99.27 37.28,95.94 43.86,95.94 v1(44.59,95.21)
  BOTTOM w0.178: v1(54.83,58.4) 54.63,58.61 54.63,74.74 44.59,84.77 v1(44.59,95.21)
SPI3_SS3_ISO: length 53.7
  TOP w0.203: v1(54.96,53.37) U25.6 ; v1(48.17,32.14) 47.74,31.71 47.74,29.14 41.95,23.35 32.65,23.35 31.77,24.24 31.77,28.08 30.87,28.98 U2.61
  BOTTOM w0.203: v1(54.96,53.37) 53.88,53.37 51.15,50.63 51.15,43.7 48.17,40.73 v1(48.17,32.14)
SPI_CFG1: length 7.1
  TOP w0.178: v1(57.23,86.9) 57.54,86.6 U8.37 ; v1(53.15,87.69) U1.120
  BOTTOM w0.178: v1(57.23,86.9) 53.94,86.9 v1(53.15,87.69)
SPIXF_SCK: length 21.9
  TOP w0.178: v1(43.17,99.78) 43.17,100.32 43.45,100.6 U1.13 ; U11.6 v1(25.13,101.3)
  BOTTOM w0.178: v1(25.13,101.3) 25.38,101.04 36.22,101.04 37.48,99.78 v1(43.17,99.78)
SPIXF_SDIO0: length 20.9
  TOP w0.178: v1(25.13,100.03) U11.5 ; U1.17 v1(41.45,99.2)
  BOTTOM w0.178: v1(25.13,100.03) 35.38,100.03 36.85,98.56 38.54,98.56 39.18,99.2 v1(41.45,99.2)
SPIXF_SDIO1: length 26
  TOP w0.178: U1.15 v1(42.45,100.39) ; v1(20.45,102.57) U11.2
  BOTTOM w0.178: v1(42.45,100.39) 41.78,101.07 38.18,101.07 37.34,101.9 26.59,101.9 25.27,103.23 21.11,103.23 v1(20.45,102.57)
SPIXF_SDIO2: length 22.7
  TOP w0.178: v1(38.16,99.17) 38.95,99.96 U1.22 ; v1(20.45,101.3) U11.3
  BOTTOM w0.178: v1(38.16,99.17) 37.11,99.17 35.69,100.59 21.16,100.59 v1(20.45,101.3)
SPIXF_SDIO3: length 16.6
  TOP w0.178: U1.23 38.45,100.73 v1(38.12,100.39) ; v1(25.13,102.57) U11.7
  BOTTOM w0.178: v1(25.13,102.57) 26.19,101.5 37.01,101.5 v1(38.12,100.39)
SPIXF_SS0: length 27.6
  TOP w0.178: U1.12 v1(43.95,100.31) ; U11.1 v1(20.57,103.84)
  BOTTOM w0.178: v1(20.57,103.84) 25.45,103.84 26.94,102.35 37.56,102.35 38.43,101.47 42.79,101.47 v1(43.95,100.31)
SPOE_OUT_O: length 3.7
  TOP w0.508: TP3.1 95.87,52.17 ; TP3.1 95.87,54.03 ; TP3.1 96.79,53.1 ; TP3.1 94.94,53.1
STBY: length 11
  TOP w0.254: U19.10 v1(92.09,54.12) 92.09,53.15 C135.1 ; U19.4 91.59,58.95 v1(91.35,59.19)
  BOTTOM w0.305: v1(91.35,59.19) 89.75,57.6 89.75,55.85 91.48,54.12 v1(92.09,54.12)
SWP: length 1.8
  TOP w0.305: 65.7,57.87 66.15,57.87 66.36,58.07 ; 65.7,57.87 65.9,58.07 ; 65.7,57.87 U25.29
SWPD_EN: length 15.4
  TOP w0.178: U1.133 49.31,94.19 v1(49.09,93.96) ; U8.33 57.55,88.6 55.94,90.22 55.94,92.58 v1(55.55,92.97)
  BOTTOM w0.178: v1(55.55,92.97) 55.15,92.57 53.48,92.57 52.09,93.96 v1(49.09,93.96)
TC: length 1.9
  TOP w0.508: U15.8 61.48,16.94 R67.2
TCK: length 37.5
  TOP w0.178: v1(49.8,83.11) 50.22,82.69 U1.110 ; P1.4 v1(71.04,96.33)
  BOTTOM w0.178: v1(71.04,96.33) 71.04,87.69 64,80.65 52.26,80.65 v1(49.8,83.11)
TMS: length 40.6
  TOP w0.178: P1.2 v1(72.31,96.33) ; U1.113 49.83,84.19 v1(49.24,83.6)
  BOTTOM w0.178: v1(72.31,96.33) 71.49,95.51 71.49,87.51 64.18,80.2 51.93,80.2 49.24,82.89 v1(49.24,83.6)
TS_CAPT: length 17
  TOP w0.178: v1(48.88,91.93) 49.14,92.19 U1.129 ; U8.40 57.8,85.1 57.52,84.82 v1(57.52,84.39)
  BOTTOM w0.178: v1(48.88,91.93) 48.88,89.47 49.52,88.83 50.38,88.83 53.25,85.97 55.94,85.97 v1(57.52,84.39)
TS_TIMER__MS_SEL: length 10.5
  TOP w0.152: U8.30 58.7,90.89 58.03,91.57 58.03,93.25 57.32,93.96 54.09,93.96 53.31,93.19 U1.131
TX2P4_EN: length 14
  TOP w0.178: v1(56.38,92.97) 56.38,90.76 57.54,89.6 U8.31 ; v1(49.57,94.94) 49.82,94.69 U1.134
  BOTTOM w0.178: v1(56.38,92.97) 55.62,93.73 53.15,93.73 52.39,94.5 50.01,94.5 v1(49.57,94.94)
TXN: length 11.3
  TOP w0.203: U8.12 69.16,85.6 69.66,85.1 R26.2 72.68,85.1 73.8,83.98 R24.1
TXP: length 11.2
  TOP w0.203: U8.15 69.53,87.1 69.78,87.35 R21.2 72.71,87.35 73.83,88.47 R22.1
UART0_RX: length 20.1
  TOP w0.152: U1.132 52.87,93.69 v1(53.48,94.29) ; P1.8 68.5,96.13 67.68,95.31 v1(55.06,95.31)
  BOTTOM w0.152: v1(55.06,95.31) 54.5,95.31 v1(53.48,94.29)
UART0_TX: length 21.3
  TOP w0.152: U1.137 53.09,96.19 54.5,94.78 68.03,94.78 69.77,96.51 P1.6
UNNAMED_2_ADMAXQ1065_I121_CEXT: length 1
  TOP w0.279: U5.1 C100.1
UNNAMED_2_ADMAXQ1065_I121_RESETOUT: length 1.1
  TOP w0.203: U5.10 R106.1
UNNAMED_2_CAP_I138_N1: length 0.7
  TOP w0.457: C180.1 R126.1
UNNAMED_2_DIOLED_I129_N: length 2.5
  TOP w0.305: DS17.C Q20.3
UNNAMED_2_DIOLED_I129_P: length 1.1
  TOP w0.305: R116.2 DS17.A
UNNAMED_2_DIOLED_I131_N: length 2.5
  TOP w0.305: Q21.3 DS18.C
UNNAMED_2_DIOLED_I131_P: length 1.1
  TOP w0.305: R117.2 DS18.A
UNNAMED_6_ADIN1110V2_I1_CEXT2: length 1.4
  TOP w0.254: C52.1 64.7,89.1 U8.19
UNNAMED_6_ADIN1110V2_I1_CEXT3: length 2.5
  TOP w0.254: U8.20 64.93,89.6 65.82,90.5 C53.1
UNNAMED_6_ADIN1110V2_I1_LED0: length 2.8
  TOP w0.254: R102.2 59.31,83.37 59.7,83.76 U8.3
UNNAMED_6_ADIN1110V2_I1_LED1: length 3.9
  TOP w0.254: U8.6 61.2,83.76 61.55,83.41 R105.2 R104.2
UNNAMED_6_ADIN1110V2_I1_TEST1: length 2
  TOP w0.203: R35.1 59.95,91.46 60.7,90.7 U8.26
UNNAMED_6_CAP_I79_N2: length 1.6
  TOP w0.305: R40.1 100.08,55.55 C119.2
UNNAMED_6_DIOLED_I64_N: length 1
  TOP w0.254: R102.1 DS10.C
UNNAMED_6_DIOLED_I147_N: length 1
  TOP w0.254: R105.1 DS11.C
UNNAMED_6_RES_I107_N1: length 1.8
  TOP w0.508: R41.1 84.14,59.43 84.14,57.98 Q11.2
UNNAMED_6_RES_I109_N1: length 1.8
  TOP w0.508: R38.1 87.16,59.42 87.16,57.97 Q10.2
UNNAMED_7_ADLT8304_I142_EN: length 3.7
  TOP w0.457: R28.1 59.4,10.66 ; R28.1 58.83,10.13 ; R28.1 59.97,10.13 ; R29.1 60.13,11.38 ; R29.1 59.4,10.78 ; R29.1 58.66,11.38
UNNAMED_7_ADLT8304_I142_RFB: length 2.4
  TOP w0.635: U15.6 64.02,17.31 R55.1
UNNAMED_7_ADLT8304_I142_RREF: length 2.7
  TOP w0.508: R54.1 R67.1 62.75,16.94 U15.7
UNNAMED_7_ADMAX17761_I143_EN: length 2.9
  TOP w0.254: R59.1 U16.4
  TOP w0.457: R49.2 R59.1
UNNAMED_7_ADMAX17761_I143_FB: length 3.4
  TOP w0.254: U16.8 66.14,76.33 65.81,76.66 R61.1 R63.1 R60.2
UNNAMED_7_ADMAX17761_I143_RESETN: length 4.3
  TOP w0.254: R64.2 73.63,75.98 73.02,76.6 70.67,76.6 70.41,76.33 U16.5
UNNAMED_7_ADMAX17761_I143_RT: length 1.4
  TOP w0.254: U16.6 69.94,76.83 70.3,77.19 R62.2
UNNAMED_7_ADMAX17761_I143_SS: length 1.6
  TOP w0.254: U16.9 C127.1
UNNAMED_7_ADP22X_I83_ADJ1: length 1.9
  TOP w0.254: U17.8 56.82,103.65 56.39,104.08 R43.2 R44.1
UNNAMED_7_ADP22X_I83_ADJ2: length 1.8
  TOP w0.254: R45.2 R46.1 U17.4
UNNAMED_7_ADP1032_I2_SYNC: length 1.4
  TOP w0.279: R56.1 59.73,51.38 U25.14
UNNAMED_7_CAP_I60_N1: length 0.8
  TOP w0.254: R63.2 C126.1
UNNAMED_7_CAP_I103_N1: length 3
  TOP w0.635: C137.1 62.2,8.72 62.75,9.28 U15.2
UNNAMED_7_DIOLED_I159_N: length 2.3
  TOP w0.483: DS12.C Q13.3
UNNAMED_7_DIOLED_I159_P: length 1.2
  TOP w0.483: DS12.A 62.8,65.03 R81.2
UNNAMED_7_RES_I152_N1: length 2.6
  TOP w0.457: v1(58.59,41.33) R47.1
  BOTTOM w0.457: S2.3 v1(58.59,41.33)
UNNAMED_7_RES_I153_N1: length 4.6
  TOP w0.457: v1(54.75,29.98) R58.1
  BOTTOM w0.457: S2.1 v1(54.75,29.98)
UNNAMED_8_DIOLED_I6_P: length 1.2
  TOP w0.254: R34.2 DS9.A
UNNAMED_8_DIOLED_I35_P: length 2.8
  TOP w0.178: R33.1 7.01,30.39 DS7.A DS8.A
UNNAMED_8_DIOLED_I37_P: length 2.8
  TOP w0.178: DS6.A DS5.A 7.01,35.47 R32.1
UNNAMED_8_DIOLED_I39_P: length 2.8
  TOP w0.178: DS4.A DS3.A 7.01,40.55 R31.1
UNNAMED_8_DIOLED_I41_P: length 2.8
  TOP w0.178: R30.1 7.01,45.63 DS1.A DS2.A
UNNAMED_9_AD74413_I30_CPUMPN: length 2.8
  TOP w0.254: U2.26 27.87,41.46 C17.2
UNNAMED_9_AD74413_I30_CPUMPP: length 2.8
  TOP w0.254: C17.1 28.87,41.47 U2.24
UNNAMED_9_DIOBAV99LT1_I116_C: length 6
  TOP w0.305: R2.2 R10.2 39.5,29.02 R17.2 39.58,27.93 40.53,26.98 CR1.3
UNNAMED_9_DIOBAV99LT1_I117_C: length 6.2
  TOP w0.305: R4.2 R12.2 39.5,39.69 R18.2 39.58,41.03 40.53,41.98 CR2.3
UNNAMED_9_DIOBAV99LT1_I118_C: length 6
  TOP w0.305: R6.2 R14.2 17.73,39.92 R19.2 17.65,41 16.7,41.95 CR3.3
UNNAMED_9_DIOBAV99LT1_I119_C: length 6.2
  TOP w0.305: R8.2 R16.2 17.73,29.24 R20.2 17.65,27.91 16.7,26.96 CR4.3
VIOUTN_A: length 12
  TOP w0.279: U2.6 35.32,33.22 v1(35.91,32.63)
  TOP w0.305: CR1.2 v1(37.72,25.35)
  BOTTOM w0.254: v1(35.91,32.63) 37.18,31.37 37.18,25.9 v1(37.72,25.35)
VIOUTN_B: length 10.3
  TOP w0.279: CR2.2 v1(38.63,41.27) ; U2.11 35.61,35.72 v1(35.94,36.05)
  BOTTOM w0.305: v1(35.94,36.05) 38.04,38.15 38.04,40.68 v1(38.63,41.27)
VIOUTN_C: length 12
  TOP w0.279: U2.38 21.91,35.72 v1(21.32,36.3)
  TOP w0.305: CR3.2 v1(19.51,43.59)
  BOTTOM w0.305: v1(19.51,43.59) 20.05,43.05 20.05,37.58 v1(21.32,36.3)
VIOUTN_D: length 10.3
  TOP w0.279: U2.43 21.62,33.22 v1(21.29,32.88) ; CR4.2 v1(18.61,27.67)
  BOTTOM w0.305: v1(21.29,32.88) 19.19,30.79 19.19,28.26 v1(18.61,27.67)
VIOUTP_A: length 11.4
  TOP w0.279: v1(35.37,32.17) 34.82,32.72 U2.5
  TOP w0.305: Q1.4 v1(35.62,25.03)
  BOTTOM w0.254: v1(35.62,25.03) 36.49,25.91 36.49,31.05 v1(35.37,32.17)
VIOUTP_B: length 8.8
  TOP w0.279: v1(35.36,36.58) 35,36.22 U2.12 ; Q2.4 v1(36.62,41.29)
  BOTTOM w0.305: v1(35.36,36.58) 35.36,36.58 37.25,38.48 37.25,40.66 v1(36.62,41.29)
VIOUTP_C: length 11.4
  TOP w0.279: U2.37 22.41,36.22 v1(21.86,36.77)
  TOP w0.305: Q3.4 v1(21.62,43.9)
  BOTTOM w0.305: v1(21.86,36.77) 20.76,37.87 20.76,43.04 v1(21.62,43.9)
VIOUTP_D: length 8.8
  TOP w0.279: Q4.4 v1(20.61,27.64) ; v1(21.87,32.36) 22.23,32.72 U2.44
  BOTTOM w0.305: v1(21.87,32.35) 19.98,30.46 19.98,28.28 v1(20.61,27.64)
VOUT1: length 3.7
  TOP w0.508: TP7.1 71.5,43.37 ; TP7.1 70.58,44.29 ; TP7.1 69.65,43.37 ; TP7.1 70.58,42.44
VOUT2: length 3.8
  TOP w0.508: TP9.1 56.99,44.61 ; TP9.1 57.93,45.54 ; TP9.1 57.93,43.68 ; TP9.1 58.94,44.61
XTAL_I: length 7.3
  TOP w0.254: Y1.1 C50.1 64.88,80.01 64.43,80.46 64.43,81.16 62.2,83.39 U8.8
XTAL_O: length 7.4
  TOP w0.254: Y1.3 C51.1 66.9,84.17 66.58,84.49 65.04,84.49 64.05,83.5 62.96,83.5 62.7,83.76 U8.9

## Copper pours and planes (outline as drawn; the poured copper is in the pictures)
1V1 on TOP: 56.56,102.6 57.39,102.6 57.62,102.83 58.33,102.83 58.33,103.39 58.94,104 58.94,105.14 58.82,105.27 57.11,105.27 56.99,105.14 56.99,104.05 57.47,103.56 57.47,103.11 57.27,102.9 56.56,102.9
1V8 on TOP: 56.48,101.9 57.39,101.9 57.72,101.57 58.59,101.57 58.59,99.64 58.4,99.45 56.08,99.45 55.89,99.64 55.89,100.99 56.39,101.5 56.39,101.81
1V8 on L2_PWR: 61.56,96.63 60.82,95.89 47.51,95.89 47.51,90.18 53.05,90.18 53.05,82.05 47.39,76.39 42.74,76.39 39.82,79.31 5.43,79.31 5.43,82.1 36.36,82.1 37.3,83.04 37.3,88.15 33.9,91.55 33.9,94.8 30.98,97.72 27.07,97.72 27.07,103.16 38.83,103.16 40.12,101.86 57.29,101.86 59.5,99.65 61.56,99.65
3V3 on TOP: 56.63,102.4 57.5,102.4 57.67,102.57 59.83,102.57 60.37,103.11 61.31,103.11 61.48,102.93 61.48,101.77 57.81,101.77 57.5,102.09 56.63,102.09
3V3 on TOP: 56.99,72.09 56.99,74.99 59.4,74.99 59.4,72.09
3V3 on L2_PWR: 1.54,105.19 74.69,105.19 74.69,92.49 70.73,88.53 69.41,88.53 69.41,92.57 65.19,92.57 62.98,90.36 62.98,89.67 58.64,89.67 58.64,85.02 60.95,85.02 60.95,83.17 63.03,81.09 63.03,79.16 62.68,78.8 61.99,78.8 59.4,76.21 59.4,69.1 61.56,66.94 61.56,64.75 60.29,63.48 59.12,63.48 57.5,61.86 54.32,61.86 54.32,70.85 52.57,72.6 1.54,72.6 ; 1 cut-out
3V3_ISO on TOP: 28.26,42.53 28.26,44.15 29.99,44.15 29.99,42.53
3V3_ISO on TOP: 60.65,45.73 60.65,42.76 61.23,42.17 62.22,42.17 62.22,45.73
3V3_ISO on L2_PWR: 1.54,69.73 1.54,47.74 8.85,47.74 11.57,50.45 11.57,62.14 13.4,63.97 19.37,63.97 24.7,58.63 32.45,58.63 35.02,61.2 42.51,61.2 46.9,56.8 46.9,54.64 51.12,50.43 51.12,42.5 61.69,42.5 63.69,44.51 63.69,48.09 65.24,49.64 65.24,54.36 53.89,54.36 51.48,56.78 51.48,68.97 50.71,69.73
3V3_O on TOP: 67.57,68.09 67.57,71.38 56.99,71.38 56.99,68.09
24V_EXT on TOP: 63.39,11.34 63.39,8.77 63.21,8.59 63.21,5.11 63.41,4.91 65.12,4.91 65.32,5.11 65.32,8.37 64.66,9.03 64.66,11.34
24V_EXT on TOP: 69.92,31.84 61.1,31.84 61.1,28.86 58.59,26.35 58.59,23.25 57.67,22.34 49.52,22.34 48.83,21.65 48.83,18.47 52.97,14.33 52.97,11.16 57.65,11.16 58.87,12.38 60.47,12.38 60.47,13.42 59.6,14.28 59.6,17.94 63.52,21.85 70.81,21.85 70.81,30.95
24V_EXT on L2_PWR: 48.88,22.77 48.88,1.89 76.72,1.89 76.72,9.48 76.34,9.86 71.74,9.86 70.96,10.65 70.96,24.16 71.87,25.08 76.06,25.08 76.55,25.56 76.55,32.77 53.71,32.77 52.09,31.15 52.09,25.97
36V on TOP: 87.44,30.69 90.39,30.69 90.39,33.23 95.04,33.23 95.65,32.62 95.65,19.44 94.02,17.81 90.13,17.81 90.13,21.68 87.44,21.68
AGND on TOP: 13.46,13.23 13.46,5.31 13.69,5.08 16.87,5.08 17.09,5.31 17.09,8.71 17.78,9.4 17.78,12.98 17.2,13.56 15.82,13.56 13.21,16.18 11.66,16.18 11.66,15.04
AGND on TOP: 21.08,13.23 21.08,5.31 21.31,5.08 24.46,5.08 24.71,5.33 24.71,8.71 25.4,9.4 25.4,12.98 24.82,13.56 23.44,13.56 20.83,16.18 19.28,16.18 19.28,15.04
AGND on TOP: 36.35,13.23 36.35,5.36 36.63,5.08 39.75,5.08 39.98,5.31 39.98,8.71 40.67,9.4 40.67,12.98 40.08,13.56 38.71,13.56 36.09,16.18 34.54,16.18 34.54,15.04
AGND on TOP: 1.02,70.29 50.97,70.29 52.06,69.2 52.06,57.06 54.19,54.92 66.49,54.92 67.05,54.36 76.29,54.36 77.13,53.53 77.13,25.15 76.55,24.57 71.92,24.57 71.41,24.06 71.41,10.91 71.92,10.4 76.55,10.4 77.16,9.79 77.16,1.02 1.02,1.02 ; 12 cut-outs
AGND on TOP: 28.73,13.23 28.73,5.36 29.01,5.08 32.08,5.08 32.36,5.36 32.36,8.71 33.05,9.4 33.05,12.98 32.46,13.56 31.09,13.56 28.47,16.18 26.92,16.18 26.92,15.04
AGND on BOTTOM: 1.02,70.29 50.97,70.29 52.06,69.2 52.06,57.06 54.19,54.92 66.49,54.92 67.05,54.36 76.29,54.36 77.13,53.53 77.13,25.15 76.55,24.57 71.92,24.57 71.41,24.06 71.41,10.88 71.92,10.37 76.55,10.37 77.13,9.79 77.13,1.02 1.02,1.02
AGND on L3_GND: 1.02,70.29 50.97,70.29 52.06,69.2 52.06,57.06 54.19,54.92 66.49,54.92 67.05,54.36 76.29,54.36 77.13,53.53 77.13,25.15 76.55,24.57 71.92,24.57 71.41,24.06 71.41,10.91 71.92,10.4 76.55,10.4 77.16,9.79 77.16,1.02 1.02,1.02 ; 7 cut-outs
DGND on TOP: 1.02,105.66 79.19,105.66 79.19,94.22 84.93,94.22 87.98,91.17 103.88,91.17 103.88,1.02 78.91,1.02 78.91,9.79 79.49,10.37 84.11,10.37 84.62,10.88 84.62,24.06 84.11,24.57 79.49,24.57 78.91,25.15 78.91,56.96 77.97,57.9 66.79,57.9 65.9,57 54.61,57 53.81,57.79 53.81,69.94 51.7,72.04 1.02,72.04 ; 9 cut-outs
DGND on BOTTOM: 1.02,105.66 79.19,105.66 79.19,94.19 84.95,94.19 87.98,91.17 103.88,91.17 103.88,1.02 78.91,1.02 78.91,9.79 79.49,10.37 84.11,10.37 84.62,10.88 84.62,24.06 84.11,24.57 79.49,24.57 78.91,25.15 78.91,56.96 77.66,58.2 67.1,58.2 65.9,57 54.61,57 53.81,57.79 53.81,69.94 51.7,72.04 1.02,72.04
DGND on L2_PWR: 1.02,105.66 79.19,105.66 79.19,94.22 84.93,94.22 87.98,91.17 103.88,91.17 103.88,1.02 78.86,1.02 78.86,9.74 79.49,10.37 84.11,10.37 84.62,10.88 84.62,24.06 84.11,24.57 79.49,24.57 78.91,25.15 78.91,56.96 77.66,58.2 67.1,58.2 65.9,57 54.61,57 53.81,57.79 53.81,69.94 51.7,72.04 1.02,72.04
DGND on L3_GND: 1.02,105.66 79.19,105.66 79.19,94.19 84.93,94.19 87.95,91.17 103.88,91.17 103.88,1.02 78.86,1.02 78.86,9.74 79.49,10.37 84.11,10.37 84.62,10.88 84.62,24.06 84.11,24.57 79.49,24.57 78.91,25.15 78.91,56.96 77.64,58.23 67.12,58.23 65.9,57 54.61,57 53.81,57.79 53.81,69.94 51.7,72.04 1.02,72.04
GND_EARTH on TOP: 90.9,105.15 90.9,97.72 91.25,97.37 92.47,97.37 92.78,97.67 92.78,105.15
GND_EARTH on TOP: 95.93,92.08 103.38,92.08 103.38,104.8 103.02,105.15 96.71,105.15 96.71,102.14 97.02,101.84 100.88,101.84 100.88,97.95 98.69,97.95 95.93,95.18
GND_EARTH on TOP: 87.26,95.03 80.1,95.03 80.1,105.15 86.96,105.15 86.96,102.14 86.65,101.84 82.79,101.84 82.79,97.95 84.98,97.95 87.26,95.67
GND_EARTH on BOTTOM, L2_PWR, L3_GND: 80.1,105.15 103.38,105.15 103.38,92.08 88.28,92.08 85.33,95.03 80.1,95.03
VDD_1 on TOP (solid shape): 39.45,55.09 39.45,53.21 38.46,53.21 38.32,53.16 38.26,53.01 38.26,52.6 36.46,52.6 36.33,52.73 36.33,53.62 35.97,53.98 35.31,53.98 34.27,55.02 32.5,55.02 32.45,55.03 32.4,55.03 31.77,55.03 31.73,55.03 31.69,55.02 31.59,55.02 31.59,55.33 31.69,55.33 31.73,55.32 31.77,55.32 32.4,55.32 32.51,55.34 32.61,55.39 32.63,55.41 39.14,55.41
VDD_2 on TOP (solid shape): 39.45,57.48 38.46,57.48 38.32,57.42 38.26,57.28 38.26,56.87 38.27,56.8 38.31,56.73 38.36,56.58 38.26,56.46 32.62,56.46 32.6,56.47 32.5,56.52 32.4,56.53 31.77,56.53 31.73,56.53 31.69,56.52 31.59,56.52 31.59,56.83 31.69,56.83 31.73,56.82 31.77,56.82 32.4,56.82 32.45,56.82 32.51,56.84 34.27,56.84 34.29,56.84 35.31,57.86 36,57.86 36.33,58.19 36.33,59.13 36.46,59.26 39.45,59.26
VDD_3 on TOP (solid shape): 20.84,59.12 20.84,58.23 21.19,57.88 21.85,57.88 22.89,56.83 24.66,56.83 24.72,56.82 24.77,56.82 25.4,56.82 25.43,56.82 25.48,56.83 25.57,56.83 25.57,56.52 25.48,56.52 25.43,56.53 25.4,56.53 24.77,56.53 24.66,56.52 24.57,56.47 24.54,56.46 18,56.46 17.66,56.8 17.66,58.65 18.65,58.65 18.8,58.71 18.85,58.85 18.85,59.25 20.71,59.25
VDD_4 on TOP (solid shape): 24.55,55.39 24.65,55.34 24.77,55.32 25.4,55.32 25.43,55.32 25.48,55.33 25.57,55.33 25.57,55.02 25.48,55.02 25.43,55.03 25.4,55.03 24.77,55.03 24.72,55.03 24.65,55.01 22.88,55.01 21.85,53.99 21.17,53.99 20.84,53.66 20.84,52.72 20.71,52.59 17.66,52.59 17.66,54.38 18.65,54.38 18.8,54.44 18.85,54.59 18.85,54.99 18.82,55.1 18.74,55.17 18.73,55.18 18.66,55.25 18.81,55.41 24.53,55.41
VDD_24V on TOP: 39.13,33.79 39.13,32.04 40.71,32.04 40.71,33.79
VDD_24V on TOP: 72.15,46.72 74.69,46.72 74.95,46.47 74.95,44.48 74.69,44.23 72.15,44.23
VDD_24V on TOP: 19.75,33.28 19.75,35.03 18.18,35.03 18.18,33.28
VDD_24V on L2_PWR: 1.54,1.91 48.4,1.91 48.4,23 51.58,26.17 51.58,31.48 53.38,33.28 76.55,33.28 76.55,53.27 76.14,53.68 65.73,53.68 65.73,49.41 64.2,47.89 64.2,44.33 61.89,42.02 48.38,42.02 45.33,45.07 45.33,47.3 43.2,49.44 40.66,49.44 38.24,47.02 16.78,47.02 11.98,42.22 11.98,32.88 10.38,31.28 10.38,26.69 9.17,25.49 1.54,25.49
VDD_24V_MAX14906 on TOP (solid shape): 30.98,52.11 30.98,52.06 31,51.99 31,51.89 31.35,51.54 31.37,51.44 31.29,51.39 31.09,51.39 30.95,51.33 30.89,51.18 30.89,50.62 30.95,50.48 31.09,50.42 31.56,50.42 31.56,50.37 34.19,50.37 35.27,49.28 35.27,48.12 34.97,47.81 33.84,47.81 32.88,48.77 29.75,48.77 29.75,50.44 30.04,50.73 30.07,50.77 30.18,50.88 30.18,52.04 30.19,52.11 30.19,52.74 30.18,52.81 30.18,52.93 30.98,52.93
VDD_24V_MAX14906 on TOP: 65.8,36.31 65.8,32.27 50.87,32.27 45.71,37.42 45.71,49.41 46.34,50.05 50.08,50.05 50.71,49.41 50.71,40.37 53.3,37.78 64.33,37.78
VDD_24V_MAX14906 on L2_PWR: 1.54,47.25 1.54,26.04 8.98,26.04 9.85,26.91 9.85,31.56 11.58,33.3 11.58,42.39 16.63,47.43 37.94,47.43 40.43,49.92 43.4,49.92 45.81,47.51 45.81,45.27 48.55,42.53 50.61,42.53 50.61,50.25 46.42,54.44 46.42,56.57 42.28,60.71 35.22,60.71 32.63,58.12 24.53,58.12 19.17,63.48 13.6,63.48 12.05,61.93 12.05,50.25 9.06,47.25
VIN_SYS on TOP: 86.17,47.56 86.17,45.6 82.92,45.6 82.67,45.86 82.67,47.3 82.92,47.56
VIN_SYS on TOP: 89.81,33.23 89.81,31.26 86.56,31.26 86.31,31.51 86.31,32.98 86.56,33.23
VIN_SYS on TOP: 66.44,65.57 66.44,60.21 65.62,59.39 65.62,58.56 65.34,58.28 64.63,58.28 64.63,58.48 64.38,58.73 64.15,58.73 64.07,58.81 64.07,65.29 64.35,65.57
VIN_SYS on TOP: 75.73,71.42 71.2,71.42 70.47,72.14 69.33,72.14 69.33,74.49 70.16,74.49 70.91,73.75 72.05,73.75 72.05,74.62 75.71,74.62 76.06,74.26 76.06,71.75
VIN_SYS on TOP: 75.11,58.21 77.67,58.21 77.67,66.79 77.37,67.09 75.77,67.09 75.46,66.79 75.46,61.41 75.11,61.05
VIN_SYS on L2_PWR: 77.49,64.96 79.9,62.54 79.9,28.66 80.43,28.13 88.74,28.13 89.14,28.53 89.14,47.84 84.09,47.84 82.46,49.46 82.46,73.64 75.25,73.64 74.54,72.93 74.54,71.28 75.17,70.65 75.17,67.98 64.76,67.98 64.12,67.34 64.12,63.56 64.46,63.23 66.36,63.23 66.72,63.59 66.72,64.55 67.12,64.96
(no net) on TOP: 97.14,74.23 97.14,65.41 94.53,65.41 94.53,67.01 93.89,67.65 93.89,74.23
(no net) on TOP: 90.24,68.94 90.24,67.62 93.44,67.62 93.44,68.94
(no net) on TOP: 31.59,57.04 31.59,57.84 33.08,57.84 33.46,58.22 33.46,59.06 33.89,59.49 35.87,59.49 36.02,59.34 36.02,58.22 35.9,58.09 35.24,58.09 34.19,57.04
(no net) on TOP: 35.27,48.12 34.97,47.81 33.84,47.81 32.88,48.77 29.75,48.77 29.75,50.45 30.18,50.88 30.18,52.93 31,52.93 31,51.89 31.56,51.33 31.56,50.37 34.19,50.37 35.27,49.28
(no net) on TOP: 25.57,56.45 25.57,56.83 22.89,56.83 21.85,57.88 21.19,57.88 20.84,58.23 20.84,59.12 20.71,59.25 17.66,59.25 17.66,56.45
